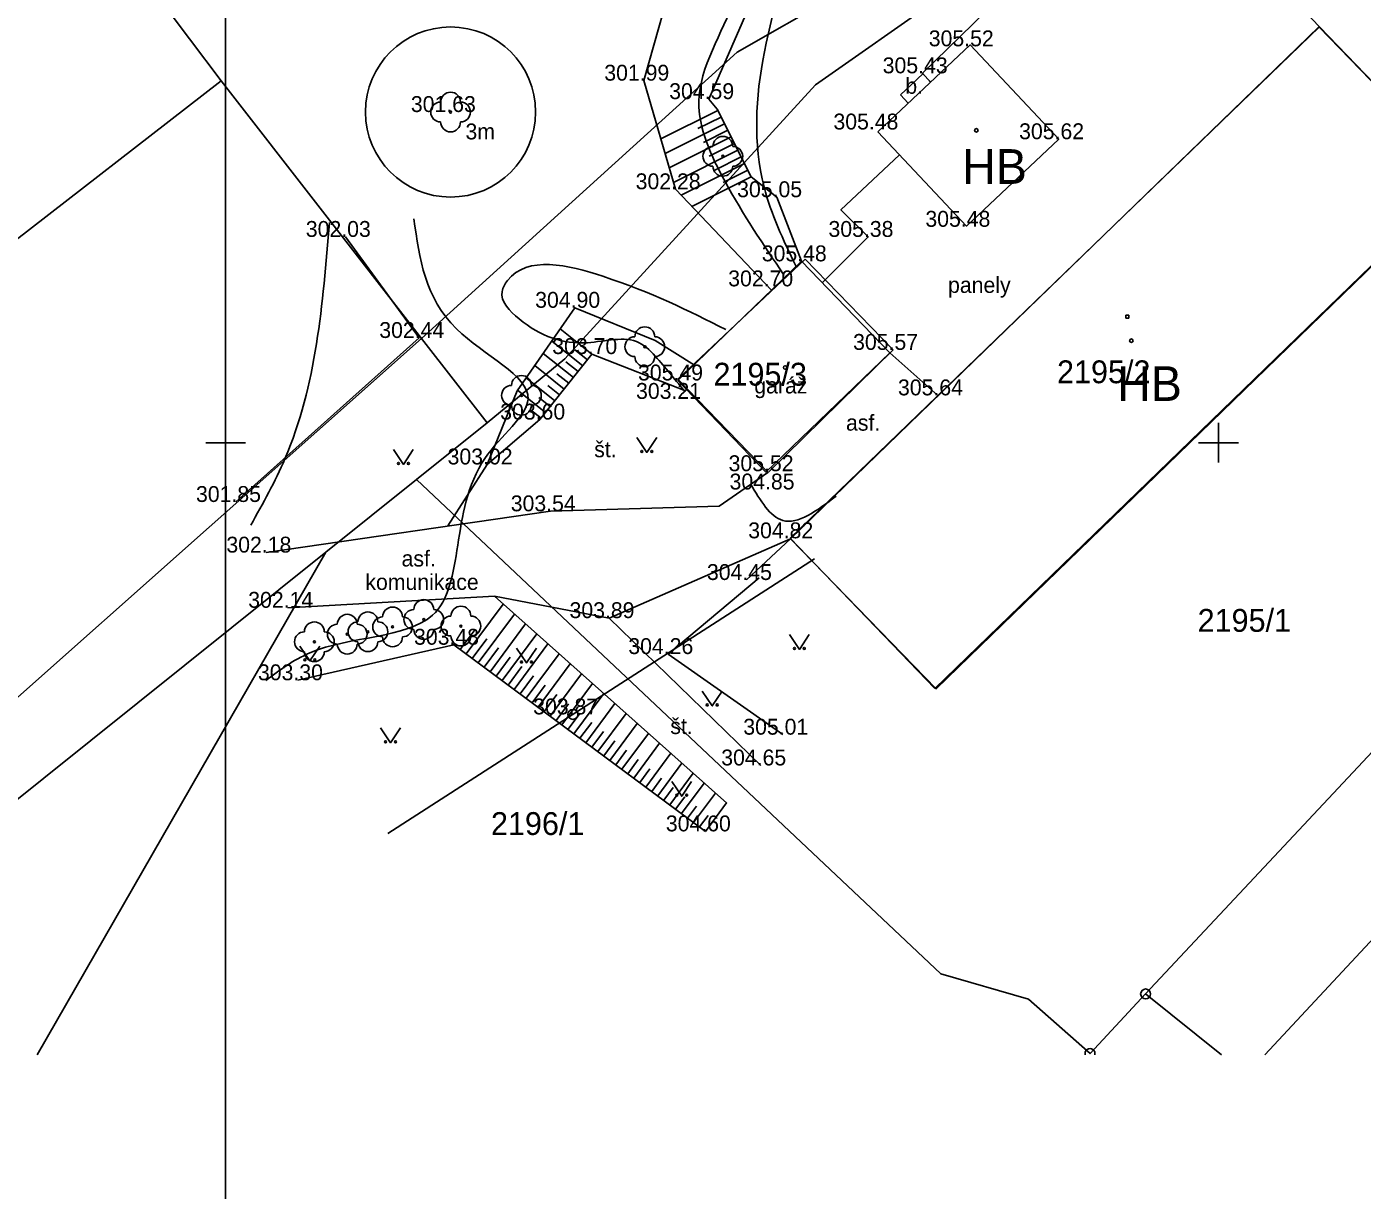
# Model space of a CAD drawing. Extents: x -504375 to -503125, y -1118000 to -1116474.
# Drawn here: x -503760 to -503692.8, y -1117237.6 to -1117179 of the extents above; entities that cross this region are included whole.
import ezdxf

# ---------------------------------------------------------------- set-up
doc = ezdxf.new("R2010")
doc.units = 0
for name, color, linetype in [('Budovy_ přístřeš', 7, 'Continuous'), ('Chodníky', 7, 'Continuous'), ('Druhy povrchů', 7, 'Continuous'), ('Elektro', 7, 'Continuous'), ('Komunikace', 7, 'Continuous'), ('Ploty', 7, 'Continuous'), ('Podkladové mapy', 7, 'Continuous'), ('Popisy budovy', 7, 'Continuous'), ('Stromy a keře', 7, 'Continuous'), ('Síť dekadická', 7, 'Continuous'), ('Vrstva 34', 7, 'Continuous'), ('Vrstva 46', 7, 'Continuous'), ('Vrstva 48', 7, 'Continuous'), ('Výškopis', 7, 'Continuous'), ('Výšky bodů plotr', 7, 'Continuous')]:
    doc.layers.add(name, color=color, linetype=linetype)

msp = doc.modelspace()

# ---------------------------------------------------------------- linework, layer by layer
at = {"layer": 'Budovy_ přístřeš'}
for points in [[(-503721.55, -1117204.84), (-503694.945, -1117179.045), (-503687.62, -1117186.6), (-503714.225, -1117212.395)], [(-503717.16, -1117184.33), (-503712.512, -1117179.957), (-503708.04, -1117184.71), (-503712.688, -1117189.083)]]:
    msp.add_lwpolyline(points, close=True, dxfattribs=at)
msp.add_lwpolyline([(-503727.23, -1117196.86), (-503721, -1117190.86), (-503716.558, -1117195.472), (-503722.788, -1117201.472), (-503727.23, -1117196.86)], dxfattribs=at)
for centre in [(-503712.193, -1117184.263), (-503704.385, -1117194.858), (-503721.824, -1117196.206)]:
    msp.add_circle(centre, 0.0875, dxfattribs=at)
at = {"layer": 'Chodníky'}
for points in [[(-503716.02, -1117182.48), (-503714.884, -1117181.412), (-503714.496, -1117181.824)], [(-503716.02, -1117182.48), (-503715.632, -1117182.892)], [(-503719.955, -1117191.945), (-503717.64, -1117189.63), (-503719.01, -1117188.26), (-503716.067, -1117185.491)], [(-503716.558, -1117195.472), (-503714.14, -1117197.61)], [(-503736.82, -1117201.09), (-503738.809, -1117204.18)]]:
    msp.add_lwpolyline(points, dxfattribs=at)
at = {"layer": 'Druhy povrchů'}
for points in [[(-503729.291, -1117199.732), (-503728.791, -1117200.482), (-503728.291, -1117199.732)], [(-503741.546, -1117200.341), (-503741.046, -1117201.091), (-503740.546, -1117200.341)], [(-503721.606, -1117209.657), (-503721.106, -1117210.407), (-503720.606, -1117209.657)], [(-503746.254, -1117210.237), (-503745.754, -1117210.987), (-503745.254, -1117210.237)], [(-503735.35, -1117210.34), (-503734.85, -1117211.09), (-503734.35, -1117210.34)], [(-503725.995, -1117212.505), (-503725.495, -1117213.255), (-503724.995, -1117212.505)], [(-503742.191, -1117214.356), (-503741.691, -1117215.106), (-503741.191, -1117214.356)], [(-503727.531, -1117217.051), (-503727.031, -1117217.801), (-503726.531, -1117217.051)]]:
    msp.add_lwpolyline(points, dxfattribs=at)
for centre in [(-503729.041, -1117200.432), (-503728.541, -1117200.432), (-503741.296, -1117201.041), (-503740.796, -1117201.041), (-503721.356, -1117210.357), (-503720.856, -1117210.357), (-503746.004, -1117210.937), (-503745.504, -1117210.937), (-503735.1, -1117211.04), (-503734.6, -1117211.04), (-503725.745, -1117213.205), (-503725.245, -1117213.205), (-503741.941, -1117215.056), (-503741.441, -1117215.056), (-503727.281, -1117217.751), (-503726.781, -1117217.751)]:
    msp.add_circle(centre, 0.05, dxfattribs=at)
at = {"layer": 'Elektro'}
msp.add_lwpolyline([(-503741.831, -1117219.686), (-503720.345, -1117205.841)], dxfattribs=at)
msp.add_circle((-503732.51, -1117213.68), 0.25, dxfattribs=at)
at = {"layer": 'Komunikace'}
for points in [[(-503747.96, -1117205.53), (-503733.64, -1117203.45), (-503725.14, -1117203.19), (-503722.7, -1117201.49)], [(-503746.86, -1117208.31), (-503736.46, -1117207.73), (-503730.68, -1117208.83), (-503721.55, -1117204.84)], [(-503724.76, -1117218.15), (-503736.46, -1117207.73)], [(-503723.04, -1117216.25), (-503730.68, -1117208.83)]]:
    msp.add_lwpolyline(points, dxfattribs=at)
at = {"layer": 'Ploty'}
for points in [[(-503692.13, -1117167.81), (-503696.45, -1117163.61), (-503703.44, -1117170.2), (-503714.91, -1117181.39), (-503714.504, -1117181.831)], [(-503749.49, -1117202.98), (-503740.26, -1117194.72), (-503743.96, -1117189.63)], [(-503721.55, -1117204.84), (-503723.76, -1117206.91)], [(-503723.135, -1117206.804), (-503727.72, -1117210.64)], [(-503725.83, -1117219.57), (-503738.51, -1117210.17), (-503746.37, -1117211.96)], [(-503727.72, -1117210.64), (-503721.93, -1117214.7)]]:
    msp.add_lwpolyline(points, dxfattribs=at)
at = {"layer": 'Podkladové mapy'}
for p, q in [((-503750.22, -1117181.77), (-503763.38, -1117164.31)), ((-503724.24, -1117180.33), (-503698.26, -1117165.42)), ((-503713.51, -1117177.21), (-503720.3, -1117181.97)), ((-503694.92, -1117179.05), (-503696.57, -1117177.3)), ((-503721.57, -1117204.81), (-503694.92, -1117179.05)), ((-503687.66, -1117186.57), (-503694.92, -1117179.05)), ((-503740.13, -1117194.75), (-503724.24, -1117180.33)), ((-503771.84, -1117198.53), (-503750.22, -1117181.77)), ((-503740.13, -1117194.75), (-503750.22, -1117181.77)), ((-503720.3, -1117181.97), (-503732.91, -1117195.77)), ((-503687.66, -1117186.57), (-503714.29, -1117212.37)), ((-503727.22, -1117196.8), (-503720.81, -1117190.75)), ((-503720.81, -1117190.75), (-503716.38, -1117195.32)), ((-503704.66, -1117193.57), (-503704.51, -1117193.57)), ((-503704.66, -1117193.72), (-503704.66, -1117193.57)), ((-503704.51, -1117193.72), (-503704.66, -1117193.72)), ((-503704.51, -1117193.57), (-503704.51, -1117193.72)), ((-503766.42, -1117218.1), (-503740.13, -1117194.75)), ((-503736.83, -1117199), (-503740.13, -1117194.75)), ((-503732.91, -1117195.77), (-503736.83, -1117199)), ((-503716.38, -1117195.32), (-503722.68, -1117201.5)), ((-503722.68, -1117201.5), (-503727.22, -1117196.8)), ((-503703.67, -1117227.76), (-503674.66, -1117196.75)), ((-503736.83, -1117199), (-503740.39, -1117201.85)), ((-503669.37, -1117200.41), (-503697.66, -1117230.829)), ((-503740.39, -1117201.85), (-503744.95, -1117205.51)), ((-503713.99, -1117226.74), (-503740.39, -1117201.85)), ((-503714.29, -1117212.37), (-503721.57, -1117204.81)), ((-503744.95, -1117205.51), (-503764.18, -1117220.91)), ((-503759.489, -1117230.829), (-503744.95, -1117205.51)), ((-503709.57, -1117228.03), (-503713.99, -1117226.74)), ((-503706.47, -1117230.76), (-503709.57, -1117228.03)), ((-503703.67, -1117227.76), (-503706.47, -1117230.76)), ((-503699.856, -1117230.829), (-503703.67, -1117227.76))]:
    msp.add_line(p, q, dxfattribs=at)
for centre, radius in [((-503703.67, -1117227.76), 0.25), ((-503703.67, -1117227.76), 0.005), ((-503706.47, -1117230.76), 0.005)]:
    msp.add_circle(centre, radius, dxfattribs=at)
msp.add_arc((-503706.47, -1117230.76), 0.25, 343.97862, 196.02138, dxfattribs=at)
at = {"layer": 'Stromy a keře'}
for centre, radius in [((-503738.67, -1117183.34), 4.284), ((-503738.67, -1117183.34), 0.05), ((-503724.96, -1117185.57), 0.05), ((-503728.89, -1117195.16), 0.05), ((-503735.1, -1117197.61), 0.05), ((-503741.592, -1117209.272), 0.05), ((-503740.02, -1117208.9), 0.05), ((-503738.15, -1117209.23), 0.05), ((-503745.53, -1117210.02), 0.05), ((-503743.873, -1117209.639), 0.05), ((-503742.832, -1117209.517), 0.05)]:
    msp.add_circle(centre, radius, dxfattribs=at)
for centre, start, end in [((-503738.67, -1117182.84), 0, 180), ((-503739.17, -1117183.34), 90, 270), ((-503738.17, -1117183.34), 270, 90), ((-503738.67, -1117183.84), 180, 0), ((-503725.46, -1117185.57), 90, 270), ((-503724.96, -1117185.07), 0, 180), ((-503724.46, -1117185.57), 270, 90), ((-503724.96, -1117186.07), 180, 0), ((-503728.89, -1117194.66), 0, 180), ((-503729.39, -1117195.16), 90, 270), ((-503728.39, -1117195.16), 270, 90), ((-503728.89, -1117195.66), 180, 0), ((-503735.6, -1117197.61), 90, 270), ((-503735.1, -1117197.11), 0, 180), ((-503734.6, -1117197.61), 270, 90), ((-503735.1, -1117198.11), 180, 0), ((-503740.02, -1117208.4), 0, 180), ((-503743.873, -1117209.139), 0, 180), ((-503742.832, -1117209.017), 0, 180), ((-503741.592, -1117208.772), 0, 180), ((-503740.52, -1117208.9), 90, 270), ((-503739.52, -1117208.9), 270, 90), ((-503738.15, -1117208.73), 0, 180), ((-503745.53, -1117209.52), 0, 180), ((-503744.373, -1117209.639), 90, 270), ((-503743.332, -1117209.517), 90, 270), ((-503743.373, -1117209.639), 270, 90), ((-503742.092, -1117209.272), 90, 270), ((-503742.332, -1117209.517), 270, 90), ((-503741.092, -1117209.272), 270, 90), ((-503738.65, -1117209.23), 90, 270), ((-503737.65, -1117209.23), 270, 90), ((-503746.03, -1117210.02), 90, 270), ((-503745.03, -1117210.02), 270, 90), ((-503742.832, -1117210.017), 180, 0), ((-503741.592, -1117209.772), 180, 0), ((-503740.02, -1117209.4), 180, 0), ((-503738.15, -1117209.73), 180, 0), ((-503745.53, -1117210.52), 180, 0), ((-503743.873, -1117210.139), 180, 0)]:
    msp.add_arc(centre, 0.5, start, end, dxfattribs=at)
at = {"layer": 'Síť dekadická'}
for points in [[(-503750, -1117000), (-503750, -1117500), (-504375, -1117500), (-504375, -1117000)], [(-503125, -1117000), (-503125, -1117500), (-503750, -1117500), (-503750, -1117000)]]:
    msp.add_lwpolyline(points, close=True, dxfattribs=at)
at = {"layer": 'Vrstva 34'}
for p, q in [((-503750, -1117199), (-503750, -1117201)), ((-503700, -1117199), (-503700, -1117201)), ((-503749, -1117200), (-503751, -1117200)), ((-503699, -1117200), (-503701, -1117200))]:
    msp.add_line(p, q, dxfattribs=at)
msp.add_lwpolyline([(-503750, -1116754.229), (-503750, -1117230.829)], dxfattribs=at)
at = {"layer": 'Vrstva 48'}
for points in [[(-503699.583, -1117147.544), (-503702.393, -1117150.08), (-503710.06, -1117155.491), (-503712.693, -1117158.826), (-503719.127, -1117165.624), (-503720.48, -1117167.771), (-503722.339, -1117172.188), (-503723.42, -1117174.604), (-503724.357, -1117177.651), (-503726.167, -1117182.804), (-503724.848, -1117186.843), (-503721.897, -1117191.523)], [(-503720.316, -1117171.519), (-503720.936, -1117173.456), (-503722.881, -1117187.116), (-503721.291, -1117191.092)], [(-503748.732, -1117204.152), (-503747.014, -1117200.806), (-503744.774, -1117188.897)], [(-503747.976, -1117211.975), (-503745.763, -1117210.582), (-503739.587, -1117208.689), (-503736.945, -1117200.796), (-503734.768, -1117197.796), (-503738.373, -1117194.261), (-503740.515, -1117188.725)], [(-503724.811, -1117194.3), (-503730.997, -1117191.615), (-503735.807, -1117191.834), (-503736.077, -1117192.375), (-503735.216, -1117193.76), (-503731.773, -1117194.959), (-503729.174, -1117194.959), (-503728.263, -1117195.752), (-503726.862, -1117197.441)], [(-503723.561, -1117202.072), (-503721.944, -1117203.913), (-503719.25, -1117202.686)]]:
    msp.add_spline(points, degree=3, dxfattribs=at)
at = {"layer": 'Výškopis'}
for p, q in [((-503725.217, -1117183.256), (-503728.084, -1117184.689)), ((-503725.049, -1117183.591), (-503726.221, -1117184.177)), ((-503724.882, -1117183.927), (-503727.872, -1117185.422)), ((-503724.714, -1117184.262), (-503725.935, -1117184.873)), ((-503724.546, -1117184.598), (-503727.661, -1117186.155)), ((-503724.379, -1117184.933), (-503725.649, -1117185.568)), ((-503724.211, -1117185.268), (-503727.449, -1117186.887)), ((-503724.043, -1117185.604), (-503725.359, -1117186.262)), ((-503723.875, -1117185.939), (-503727.062, -1117187.533)), ((-503723.708, -1117186.275), (-503724.941, -1117186.891)), ((-503723.54, -1117186.61), (-503726.521, -1117188.1)), ((-503731.55, -1117195.53), (-503733.148, -1117194.262)), ((-503732.016, -1117196.117), (-503733.577, -1117194.879)), ((-503732.483, -1117196.705), (-503734.005, -1117195.496)), ((-503731.783, -1117195.824), (-503732.415, -1117195.322)), ((-503732.949, -1117197.292), (-503734.434, -1117196.113)), ((-503732.716, -1117196.998), (-503733.317, -1117196.521)), ((-503732.25, -1117196.411), (-503732.866, -1117195.922)), ((-503733.415, -1117197.88), (-503734.863, -1117196.73)), ((-503733.182, -1117197.586), (-503733.769, -1117197.12)), ((-503733.882, -1117198.467), (-503735.292, -1117197.347)), ((-503733.649, -1117198.173), (-503734.22, -1117197.72)), ((-503734.115, -1117198.761), (-503734.648, -1117198.337)), ((-503737.88, -1117210.637), (-503736.017, -1117208.124)), ((-503737.277, -1117211.084), (-503735.455, -1117208.625)), ((-503736.675, -1117211.53), (-503734.892, -1117209.126)), ((-503738.181, -1117210.414), (-503737.428, -1117209.398)), ((-503737.579, -1117210.86), (-503736.842, -1117209.866)), ((-503736.072, -1117211.977), (-503734.33, -1117209.627)), ((-503736.976, -1117211.307), (-503736.255, -1117210.334)), ((-503735.47, -1117212.424), (-503733.768, -1117210.128)), ((-503734.867, -1117212.87), (-503733.205, -1117210.628)), ((-503736.374, -1117211.754), (-503735.669, -1117210.803)), ((-503735.771, -1117212.2), (-503735.082, -1117211.271)), ((-503734.265, -1117213.317), (-503732.643, -1117211.129)), ((-503735.169, -1117212.647), (-503734.496, -1117211.739)), ((-503733.662, -1117213.764), (-503732.081, -1117211.63)), ((-503734.566, -1117213.094), (-503733.91, -1117212.208)), ((-503733.964, -1117213.54), (-503733.323, -1117212.676)), ((-503733.06, -1117214.21), (-503731.518, -1117212.131)), ((-503732.457, -1117214.657), (-503730.956, -1117212.632)), ((-503733.361, -1117213.987), (-503732.737, -1117213.144)), ((-503731.855, -1117215.104), (-503730.394, -1117213.133)), ((-503732.759, -1117214.434), (-503732.15, -1117213.613)), ((-503731.252, -1117215.55), (-503729.832, -1117213.633)), ((-503732.156, -1117214.88), (-503731.564, -1117214.081)), ((-503731.554, -1117215.327), (-503730.977, -1117214.549)), ((-503730.65, -1117215.997), (-503729.269, -1117214.134)), ((-503730.047, -1117216.443), (-503728.707, -1117214.635)), ((-503730.951, -1117215.773), (-503730.391, -1117215.018)), ((-503729.445, -1117216.89), (-503728.145, -1117215.136)), ((-503730.349, -1117216.22), (-503729.804, -1117215.486)), ((-503729.746, -1117216.667), (-503729.218, -1117215.954)), ((-503728.842, -1117217.337), (-503727.582, -1117215.637)), ((-503729.144, -1117217.113), (-503728.631, -1117216.423)), ((-503728.24, -1117217.783), (-503727.02, -1117216.137)), ((-503727.637, -1117218.23), (-503726.457, -1117216.638)), ((-503728.541, -1117217.56), (-503728.045, -1117216.891)), ((-503727.939, -1117218.007), (-503727.459, -1117217.359)), ((-503727.035, -1117218.677), (-503725.895, -1117217.139)), ((-503727.336, -1117218.453), (-503726.872, -1117217.827)), ((-503726.432, -1117219.123), (-503725.333, -1117217.64)), ((-503726.734, -1117218.9), (-503726.286, -1117218.296)), ((-503726.131, -1117219.347), (-503725.699, -1117218.764)), ((-503725.83, -1117219.57), (-503724.77, -1117218.141))]:
    msp.add_line(p, q, dxfattribs=at)
for points in [[(-503722.507, -1117192.312), (-503727.35, -1117187.23), (-503728.93, -1117181.76), (-503725.48, -1117169.51), (-503721.46, -1117163.42)], [(-503725.25, -1117183.19), (-503725.66, -1117182.69), (-503722.83, -1117176.18)], [(-503723.54, -1117186.61), (-503725.25, -1117183.19)], [(-503721, -1117190.86), (-503722.24, -1117187.63), (-503723.54, -1117186.61)], [(-503736.82, -1117201.09), (-503735.32, -1117197.388), (-503732.41, -1117193.2), (-503728.374, -1117194.84), (-503726.389, -1117196.097)], [(-503731.55, -1117195.53), (-503734.17, -1117198.83)], [(-503726.84, -1117197.38), (-503731.55, -1117195.53)], [(-503734.17, -1117198.83), (-503736.82, -1117201.09)]]:
    msp.add_lwpolyline(points, dxfattribs=at)

# ---------------------------------------------------------------- texts
at = {"layer": 'Druhy povrchů'}
for s, p in [('b.', (-503715.77, -1117182.422)), ('panely', (-503713.618, -1117192.45)), ('asf.', (-503718.757, -1117199.389)), ('št.', (-503731.437, -1117200.726)), ('asf.', (-503741.138, -1117206.23)), ('št.', (-503727.604, -1117214.668))]:
    msp.add_text(s, height=0.8, dxfattribs=at).set_placement(p)
at = {"layer": 'Podkladové mapy'}
for s, p in [('2195/2', (-503708.13, -1117197)), ('2195/3', (-503725.43, -1117197.12)), ('2195/1', (-503701.05, -1117209.52)), ('2196/1', (-503736.635, -1117219.753))]:
    msp.add_text(s, height=1.15, dxfattribs=at).set_placement(p)
at = {"layer": 'Popisy budovy'}
for s, p in [('garáž', (-503723.376, -1117197.515)), ('komunikace', (-503742.962, -1117207.41))]:
    msp.add_text(s, height=0.8, dxfattribs=at).set_placement(p)
at = {"layer": 'Stromy a keře'}
msp.add_text('3m', height=0.8, dxfattribs=at).set_placement((-503737.92, -1117184.72))
at = {"layer": 'Vrstva 46'}
for p in [(-503712.901, -1117186.96), (-503705.095, -1117197.893)]:
    msp.add_text('HB', height=1.75, dxfattribs=at).set_placement(p)
at = {"layer": 'Výšky bodů plotr'}
for s, p in [('305.52 ', (-503714.59, -1117180.03)), ('301.99 ', (-503730.93, -1117181.76)), ('305.43 ', (-503716.91, -1117181.39)), ('304.59 ', (-503727.66, -1117182.69)), ('301.63 ', (-503740.67, -1117183.34)), ('305.48 ', (-503719.39, -1117184.22)), ('305.62 ', (-503710.04, -1117184.71)), ('302.28 ', (-503729.35, -1117187.23)), ('305.05 ', (-503724.24, -1117187.63)), ('305.48 ', (-503714.76, -1117189.12)), ('302.03 ', (-503745.96, -1117189.63)), ('305.38 ', (-503719.64, -1117189.63)), ('305.48 ', (-503723, -1117190.86)), ('302.70 ', (-503724.69, -1117192.12)), ('304.90 ', (-503734.41, -1117193.2)), ('302.44 ', (-503742.26, -1117194.72)), ('305.57 ', (-503718.4, -1117195.32)), ('303.70 ', (-503733.55, -1117195.53)), ('305.49 ', (-503729.23, -1117196.86)), ('303.21 ', (-503729.33, -1117197.788)), ('305.64 ', (-503716.14, -1117197.61)), ('303.60 ', (-503736.17, -1117198.83)), ('303.02 ', (-503738.82, -1117201.09)), ('305.52 ', (-503724.67, -1117201.43)), ('304.85 ', (-503724.62, -1117202.352)), ('301.85 ', (-503751.49, -1117202.98)), ('303.54 ', (-503735.64, -1117203.45)), ('304.82 ', (-503723.68, -1117204.81)), ('302.18 ', (-503749.96, -1117205.53)), ('304.45 ', (-503725.76, -1117206.91)), ('302.14 ', (-503748.86, -1117208.31)), ('303.89 ', (-503732.68, -1117208.83)), ('303.48 ', (-503740.51, -1117210.17)), ('304.26 ', (-503729.72, -1117210.64)), ('303.30 ', (-503748.37, -1117211.96)), ('303.87 ', (-503734.51, -1117213.68)), ('305.01 ', (-503723.93, -1117214.7)), ('304.65 ', (-503725.04, -1117216.25)), ('304.60 ', (-503727.83, -1117219.57))]:
    msp.add_text(s, height=0.8, dxfattribs=at).set_placement(p)

doc.saveas('drawing.dxf')
